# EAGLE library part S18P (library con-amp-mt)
AMP MT CONNECTOR
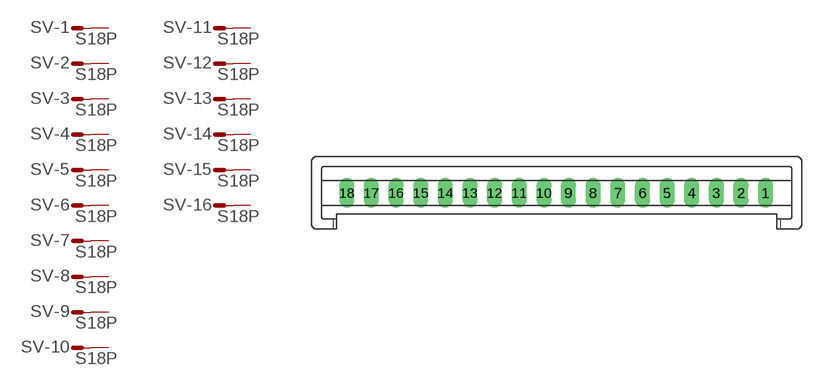
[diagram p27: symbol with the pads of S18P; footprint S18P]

Designator prefix SV; gates -1=M -2=M -3=M -4=M -5=M -6=M -7=M -8=M -9=M -10=M -11=M -12=M -13=M -14=M -15=M -16=M -17=M -18=M

## S18P (OC_FARNELL: unknown; OC_NEWARK: unknown)  [S18P]
1  -1:S  pas
2  -2:S  pas
3  -3:S  pas
4  -4:S  pas
5  -5:S  pas
6  -6:S  pas
7  -7:S  pas
8  -8:S  pas
9  -9:S  pas
10  -10:S  pas
11  -11:S  pas
12  -12:S  pas
13  -13:S  pas
14  -14:S  pas
15  -15:S  pas
16  -16:S  pas
17  -17:S  pas
18  -18:S  pas

## Footprint S18P (pad centres in mm)
AMP MT CONNECTOR
drill 1.016 long: 1 21.25,0; 2 18.75,0; 3 16.25,0; 4 13.75,0; 5 11.25,0; 6 8.75,0; 7 6.25,0; 8 3.75,0; 9 1.25,0; 10 -1.25,0; 11 -3.75,0; 12 -6.25,0; 13 -8.75,0; 14 -11.25,0; 15 -13.75,0; 16 -16.24,0; 17 -18.755,0; 18 -21.244,0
